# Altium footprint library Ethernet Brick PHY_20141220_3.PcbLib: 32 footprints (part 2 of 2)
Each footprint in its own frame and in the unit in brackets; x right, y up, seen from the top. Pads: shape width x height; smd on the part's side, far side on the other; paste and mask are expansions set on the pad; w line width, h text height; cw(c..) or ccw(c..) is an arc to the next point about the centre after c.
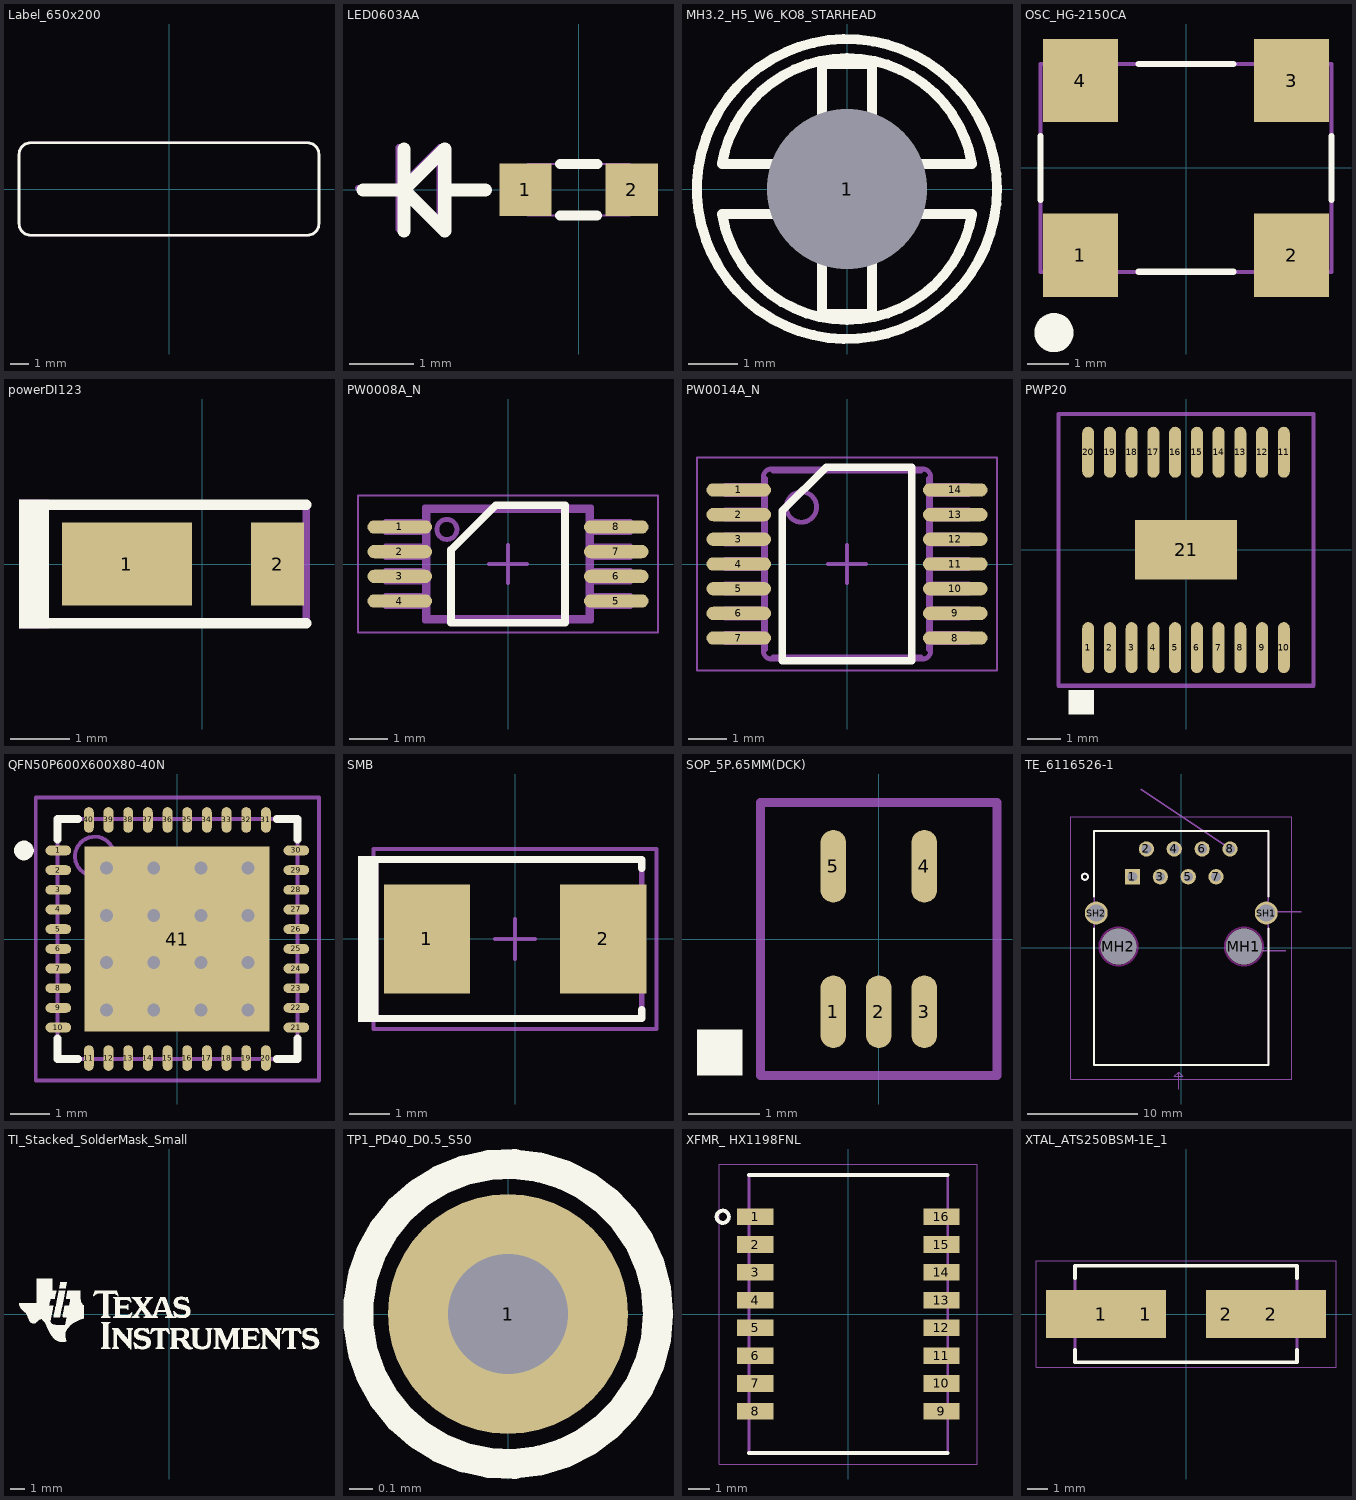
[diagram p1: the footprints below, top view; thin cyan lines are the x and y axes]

## Label_650x200 [mil] "Thermal Transfer Label"
height 1
pads (1):
  round 1 on Mech13: 0(0,0)
Top Overlay:
  lines w6: -325,-75 ccw(c-300,-75) -300,-100 300,-100 ccw(c300,-75) 325,-75 325,75 ccw(c300,75) 300,100 -300,100 ccw(c-300,75) -325,75 -325,-75
Mechanical 5:
  lines w5: -325,-75 ccw(c-300,-75) -300,-100 300,-100 ccw(c300,-75) 325,-75 325,75 ccw(c300,75) 300,100 -300,100 ccw(c-300,75) -325,75 -325,-75
  text ".Designator" at -43,-19.85 h32
3D body: height 1, standoff 0, extent -325.51,-100.51 325.51,100.51

## LED0603AA [mil]
height 35.43
pads (2):
  rect 32x32 smd: 1(-32.48,0) 2(32.48,0)
Top Overlay:
  lines w6: -11.42,-15.75 11.42,-15.75 ; -11.42,15.75 11.42,15.75
  lines w8: -131.79,-0.04 -106.79,-0.04 ; -106.79,-25.04 -106.79,24.96 ; -81.79,-0.04 -56.79,-0.04 ; -106.79,-0.04 -81.79,-25.04 -81.79,24.96 -106.79,-0.04
Mechanical 15:
  lines w1: -31.5,-15.75 -31.5,15.75 31.5,15.75 31.5,-15.75 -31.5,-15.75
  lines w3.94: -134.79,0.96 -109.79,0.96 ; -109.79,-24.04 -109.79,25.96 ; -84.79,0.96 -59.79,0.96 ; -109.79,0.96 -84.79,-24.04 -84.79,25.96 -109.79,0.96

## MH3.2_H5_W6_KO8_STARHEAD [mil]
height 80
pads (1):
  round 20 / inner round 142 / far side round 20 hole 128 unplated mask+68: 1(0,0)
Top Overlay:
  circle w8: c0,0 r120
  lines w8: -100,-20 -20,-20 -20,-100 20,-100 20,-20 100,-20 ; -100.02,-19.91 ccw(c0,-3.35) 99.99,-20.08 ; -100,20 -20,20 -20,100 20,100 20,20 100,20 ; -99.99,20.09 cw(c0,3.36) 100.02,19.92

## OSC_HG-2150CA [mm]
height 1.4
pads (4):
  rect 1.8x2 smd: 1(-2.54,-2.1) 2(2.54,-2.1) 3(2.54,2.1) 4(-2.54,2.1)
Top Overlay:
  circle w0.635: c-3.175,-3.962 r0.152
  lines w0.152: -3.5,-0.762 -3.5,0.762 ; -1.143,-2.5 1.143,-2.5 ; -1.143,2.5 1.143,2.5 ; 3.5,-0.762 3.5,0.762
Mechanical 5:
  circle w0.1: c-2.55,-2.075 r0.2
  lines w0.1: -3.5,-2.5 -3.5,2.5 3.5,2.5 3.5,-2.5 -3.5,-2.5
  text ".Designator" at 0.711,0.225 h0.91
3D body: height 1.2, standoff 1.1, extent -2.685,-2.22 -2.411,-1.946
3D body: height 1.4, standoff 0, extent -3.5,-2.5 3.5,2.5
3D body: height 1.4, standoff 1.1, extent -3.5,-2.5 3.5,2.5

## powerDI123 [mm] "Diodes Inc recommended land pattern, document number DS30628 Rev. 6-2"
height 1
pads (2):
  rect 2.2x1.4 smd: 1(-1.275,0)
  rect 0.9x1.4 smd: 2(1.275,0)
Top Overlay:
  rectangle: -3.099,-1.092 -2.591,1.092
  lines w0.178: -2.946,-1.003 1.759,-1.003 ; -2.946,1.003 1.759,1.003
Mechanical 5:
  rectangle: -3.099,-1.092 -2.591,1.092
  lines w0.127: -2.946,-1.003 1.759,-1.003 1.759,1.003 -2.946,1.003
  text ".Designator" at -1.139,-0.406 h0.91
3D body: height 1, standoff 0, extent -2.375,-0.965 1.525,0.965

## PW0008A_N [mm] "TSOP, 8-Leads, Body 3x4.4mm, Pitch 0.65mm, IPC Medium Density"
height 1.2
pads (8):
  oval 1.7x0.35 smd: 1(-2.85,0.975) 2(-2.85,0.325) 3(-2.85,-0.325) 4(-2.85,-0.975) 5(2.85,-0.975) 6(2.85,-0.325) 7(2.85,0.325) 8(2.85,0.975)
Top Overlay:
  lines w0.2: -1.5,-1.55 1.5,-1.55 1.5,1.55 -0.325,1.55 -1.5,0.375 -1.5,-1.55
Mechanical 5:
  lines w0.127: -2.2,-1.5 -2.11,-1.41 ; -2.2,-1.5 2.2,-1.5 ; -2.2,-1.5 -2.2,-1.125 ; -2.2,-1.125 -2.2,-0.825 ; -2.2,-1.125 -2.4,-1.125 -2.669,-1.125 -2.785,-1.125 -2.856,-1.125 -3.228,-1.125 -3.228,-0.825 -2.856,-0.825 -2.785,-0.825 -2.669,-0.825 -2.4,-0.825 -2.2,-0.825 ; -2.2,-0.825 -2.2,-0.475 ; -2.2,-0.475 -2.4,-0.475 -2.669,-0.475 -2.785,-0.475 -2.856,-0.475 -3.228,-0.475 -3.228,-0.175 -2.856,-0.175 -2.785,-0.175 -2.669,-0.175 -2.4,-0.175 -2.2,-0.175 ; -2.2,-0.475 -2.2,-0.175 ; -2.2,-0.175 -2.2,0.175 ; -2.2,0.175 -2.2,0.475 ; -2.2,0.175 -2.4,0.175 -2.669,0.175 -2.785,0.175 -2.856,0.175 -3.228,0.175 -3.228,0.475 -2.856,0.475 -2.785,0.475 -2.669,0.475 -2.4,0.475 -2.2,0.475 ; -2.2,0.475 -2.2,0.825 ; -2.2,0.825 -2.4,0.825 -2.669,0.825 -2.785,0.825 -2.856,0.825 -3.228,0.825 -3.228,1.125 -2.856,1.125 -2.785,1.125 -2.669,1.125 -2.4,1.125 -2.2,1.125 ; -2.2,0.825 -2.2,1.125 ; -2.2,1.125 -2.2,1.5 ; -2.2,1.5 -2.11,1.41 ; -2.2,1.5 2.2,1.5 ; -2.11,-1.41 -2.11,1.41 ; -2.11,-1.41 2.11,-1.41 ; -2.11,1.41 2.11,1.41 ; 2.11,-1.41 2.11,1.41 ; 2.11,-1.41 2.2,-1.5 ; 2.11,1.41 2.2,1.5 ; 2.2,-1.5 2.2,-1.125 ; 2.2,-1.125 2.2,-0.825 ; 2.2,-1.125 2.4,-1.125 2.669,-1.125 2.785,-1.125 2.856,-1.125 3.228,-1.125 3.228,-0.825 2.856,-0.825 2.785,-0.825 2.669,-0.825 2.4,-0.825 2.2,-0.825 ; 2.2,-0.825 2.2,-0.475 ; 2.2,-0.475 2.2,-0.175 ; 2.2,-0.475 2.4,-0.475 2.669,-0.475 2.785,-0.475 2.856,-0.475 3.228,-0.475 3.228,-0.175 2.856,-0.175 2.785,-0.175 2.669,-0.175 2.4,-0.175 2.2,-0.175 ; 2.2,-0.175 2.2,0.175 ; 2.2,0.175 2.4,0.175 2.669,0.175 2.785,0.175 2.856,0.175 3.228,0.175 3.228,0.475 2.856,0.475 2.785,0.475 2.669,0.475 2.4,0.475 2.2,0.475 ; 2.2,0.175 2.2,0.475 ; 2.2,0.475 2.2,0.825 ; 2.2,0.825 2.4,0.825 2.669,0.825 2.785,0.825 2.856,0.825 3.228,0.825 3.228,1.125 2.856,1.125 2.785,1.125 2.669,1.125 2.4,1.125 2.2,1.125 ; 2.2,0.825 2.2,1.125 ; 2.2,1.125 2.2,1.5 ; -1.61,0.646 cw(c-1.61,0.91) -1.61,1.173 cw(c-1.61,0.91) -1.61,0.646
  text ".Designator" at -0.838,-0.381 h0.91
Mechanical 15:
  lines w0.05: -3.95,-1.8 -3.95,1.8 3.95,1.8 3.95,-1.8 -3.95,-1.8
  lines w0.1: -0.5,0 0.5,0 ; 0,-0.5 0,0.5
3D body: height 1.2, standoff 0, extent -3.228,-1.5 3.228,1.5

## PW0014A_N [mm] "TSOP, 14-Leads, Body 5x4.4mm, Pitch 0.65mm, IPC Medium Density"
height 1.2
pads (14):
  oval 1.7x0.35 smd: 1(-2.85,1.95) 2(-2.85,1.3) 3(-2.85,0.65) 4(-2.85,0) 5(-2.85,-0.65) 6(-2.85,-1.3) 7(-2.85,-1.95) 8(2.85,-1.95) 9(2.85,-1.3) 10(2.85,-0.65) 11(2.85,0) 12(2.85,0.65) 13(2.85,1.3) 14(2.85,1.95)
Top Overlay:
  lines w0.2: -1.7,-2.55 1.7,-2.55 1.7,2.55 -0.55,2.55 -1.7,1.4 -1.7,-2.55
Mechanical 5:
  drawing of 182 lines, arcs and shapes, not listed
  text ".Designator" at 0.432,-0.787 h0.91
Mechanical 15:
  lines w0.05: -3.95,-2.8 -3.95,2.8 3.95,2.8 3.95,-2.8 -3.95,-2.8
  lines w0.1: -0.5,0 0.5,0 ; 0,-0.5 0,0.5
3D body: height 0.98, standoff -0.02, extent -3.21,-2.5 3.21,2.5

## PWP20 [mil]
pads (21):
  oval 14x60 smd: 1(-115.16,-115) 2(-89.57,-115) 3(-63.98,-115) 4(-38.39,-115) 5(-12.8,-115) 6(12.8,-115) 7(38.39,-115) 8(63.98,-115) 9(89.57,-115) 10(115.16,-115) 11(115.16,115) 12(89.57,115) 13(63.98,115) 14(38.39,115) 15(12.8,115) 16(-12.8,115) 17(-38.39,115) 18(-63.98,115) 19(-89.57,115) 20(-115.16,115)
  rect 120x70 smd: 21(0,0)
Top Overlay:
  region: -138,-165.4 -138,-193.15 -108.4,-193.15 -108.4,-165.4
Mechanical 5:
  lines w5: -150,-160 150,-160 150,160 -150,160 -150,-160
  text ".Designator" at 28,14.85 h36
  text "*" at -135,-88.4 h36

## QFN50P600X600X80-40N [mm] "QFN, 40-Leads, Body 6.1x6.1mm (max), Pitch 0.50mm, IPC Medium Density"
height 0.8
pads (41):
  oval 0.65x0.25 smd: 1(-3.025,2.25) 2(-3.025,1.75) 3(-3.025,1.25) 4(-3.025,0.75) 5(-3.025,0.25) 6(-3.025,-0.25) 7(-3.025,-0.75) 8(-3.025,-1.25) 9(-3.025,-1.75) 10(-3.025,-2.25) 21(3.025,-2.25) 22(3.025,-1.75) 23(3.025,-1.25) 24(3.025,-0.75) 25(3.025,-0.25) 26(3.025,0.25) 27(3.025,0.75) 28(3.025,1.25) 29(3.025,1.75) 30(3.025,2.25)
  oval 0.25x0.65 smd: 11(-2.25,-3.025) 12(-1.75,-3.025) 13(-1.25,-3.025) 14(-0.75,-3.025) 15(-0.25,-3.025) 16(0.25,-3.025) 17(0.75,-3.025) 18(1.25,-3.025) 19(1.75,-3.025) 20(2.25,-3.025) 31(2.25,3.025) 32(1.75,3.025) 33(1.25,3.025) 34(0.75,3.025) 35(0.25,3.025) 36(-0.25,3.025) 37(-0.75,3.025) 38(-1.25,3.025) 39(-1.75,3.025) 40(-2.25,3.025)
  rect 4.7x4.7 smd: 41(-0.006,0)
via -1.8,1.8 diameter 0.66 hole 0.33
via -0.6,1.8 diameter 0.66 hole 0.33
via 0.6,1.8 diameter 0.66 hole 0.33
via 1.8,1.8 diameter 0.66 hole 0.33
via -1.8,0.6 diameter 0.66 hole 0.33
via -0.6,0.6 diameter 0.66 hole 0.33
via 0.6,0.6 diameter 0.66 hole 0.33
via 1.8,0.6 diameter 0.66 hole 0.33
via -1.8,-0.6 diameter 0.66 hole 0.33
via -0.6,-0.6 diameter 0.66 hole 0.33
via 0.6,-0.6 diameter 0.66 hole 0.33
via 1.8,-0.6 diameter 0.66 hole 0.33
via -1.8,-1.8 diameter 0.66 hole 0.33
via -0.6,-1.8 diameter 0.66 hole 0.33
via 0.6,-1.8 diameter 0.66 hole 0.33
via 1.8,-1.8 diameter 0.66 hole 0.33
Top Overlay:
  circle w0.25: c-3.9,2.25 r0.125
  lines w0.2: -3.05,-2.525 -3.05,-3.05 -2.525,-3.05 ; -3.05,2.525 -3.05,3.05 -2.525,3.05 ; 2.525,-3.05 3.05,-3.05 3.05,-2.525 ; 2.525,3.05 3.05,3.05 3.05,2.525
Mechanical 13:
  circle w0.1: c-2.1,2.1 r0.5
  lines w0.1: -3.05,-3.05 -3.05,3.05 3.05,3.05 3.05,-3.05 -3.05,-3.05
Mechanical 15:
  lines w0.1: -0.5,0 0.5,0 ; 0,-0.5 0,0.5 ; -3.6,-3.6 -3.6,3.6 3.6,3.6 3.6,-3.6 -3.6,-3.6
3D body: height 0.8, standoff 0.1, extent -3.05,-3.05 3.05,3.05

## SMB [mm] "Molded Diode, 2-Leads, Body 5.4x3.6mm, IPC Medium Density, based on OnSemi component dimensions"
height 2.45
pads (2):
  rect 2.159x2.743 smd: 1(-2.21,0) 2(2.21,0)
Top Overlay:
  rectangle: -3.937,-2.083 -3.429,2.083
  lines w0.178: -3.607,-1.994 3.175,-1.994 3.175,-1.765 ; -3.607,1.994 3.175,1.994 3.175,1.765
Mechanical 5:
  rectangle: -3.937,-2.083 -3.429,2.083
  lines w0.127: -3.607,-1.994 3.175,-1.994 3.175,-1.765 3.175,1.765 3.175,1.994 -3.607,1.994
  text ".Designator" at -0.813,-0.508 h0.91
Mechanical 15:
  lines w0.1: -0.5,0 0.5,0 ; 0,-0.5 0,0.5 ; -3.55,-2.25 -3.55,2.25 3.55,2.25 3.55,-2.25 -3.55,-2.25
3D body: height 2.32, standoff 0.02, extent -2.7,-1.8 2.7,1.8

## SOP_5P.65MM(DCK) [mil]
pads (5):
  oval 14x40 smd mask+2: 1(-25,-40) 2(0,-40) 3(25,-40) 4(25,40) 5(-25,40)
Top Overlay:
  region: -100,-75 -75,-75 -75,-50 -100,-50
Mechanical 5:
  lines w5: -65,-75 -65,75 65,75 65,-75 -65,-75
  text ".Designator" at 20,17 h36
  text "*" at -55,-75 h36

## TE_6116526-1 [mm] "CONNECTOR, MODULAR JACK SHIELDED R/A, THRU-8 PIN"
height 13.63
pads (12):
  rect 1.39x1.39 hole 0.89: 1(-4.445,6.48)
  round 1.39 hole 0.89: 2(-3.175,9.02) 3(-1.905,6.48) 4(-0.635,9.02) 5(0.635,6.48) 6(1.905,9.02) 7(3.175,6.48) 8(4.445,9.02)
  round 3.25 hole 3.25 unplated mask+0.305: MH1(5.715,0.13) MH2(-5.715,0.13)
  round 2.08 hole 1.58: SH1(7.745,3.18) SH2(-7.745,3.18)
Top Overlay:
  circle w0.178: c-8.774,6.485 r0.279
  lines w0.178: -7.93,1.781 -7.93,-10.67 7.93,-10.67 7.93,1.781 ; -7.93,4.702 -7.93,10.671 7.93,10.67 7.93,4.702
Bottom Overlay:
  lines w0.178: -7.93,-9.274 -7.93,-10.67 -6.534,-10.67 ; -7.93,-8.004 -7.93,-6.607 ; -7.93,-5.972 -7.93,-4.702 ; -7.93,-1.032 -7.93,0.238 ; -7.93,1.127 -7.93,1.781 ; -7.93,4.702 -7.93,5.972 ; -7.93,6.607 -7.93,8.004 ; -7.93,9.274 -7.93,10.67 -6.534,10.67 ; -7.929,-3.629 -7.929,-2.359 ; -5.264,-10.67 -3.867,-10.67 ; -5.264,10.67 -3.867,10.67 ; -3.232,-10.67 -1.962,-10.67 ; -3.232,10.67 -1.962,10.67 ; -0.762,-10.669 0.508,-10.669 ; -0.762,10.671 0.508,10.671 ; 1.962,-10.67 3.232,-10.67 ; 1.962,10.67 3.232,10.67 ; 3.867,-10.67 5.264,-10.67 ; 3.867,10.67 5.264,10.67 ; 6.534,-10.67 7.93,-10.67 7.93,-9.274 ; 6.534,10.67 7.93,10.67 7.93,9.274 ; 7.93,-8.004 7.93,-6.607 ; 7.93,-5.972 7.93,-4.702 ; 7.93,-1.156 7.93,0.114 ; 7.93,1.127 7.93,1.781 ; 7.93,4.702 7.93,5.972 ; 7.93,6.607 7.93,8.004 ; 7.931,-3.502 7.931,-2.232
Keep-Out Layer:
  circle w0.178: c-5.715,0.13 r1.727
  circle w0.178: c5.715,0.13 r1.727
Mechanical 5:
  circle w0.127: c-8.774,6.485 r0.279
  lines w0.127: -7.93,-10.67 7.93,-10.67 7.93,10.67 -7.93,10.67 -7.93,-10.67
  text ".Designator" at -0.787,2.365 h0.91
Mechanical 15:
  lines w0.05: -10.055,-11.94 -10.055,11.94 10.055,11.94 10.055,-11.94 -10.055,-11.94
Mechanical 16:
  lines w0.05: -0.245,-12.848 -0.245,-11.324 ; -0.245,-11.324 0.136,-11.705 -0.626,-11.705 -0.245,-11.324
  lines w0.127: -3.683,14.478 4.445,9.02 ; 6.985,-0.254 9.525,-0.254 ; 8.382,3.302 10.922,3.302
Mechanical 17:
  text "MATING CONNECTOR SIDE" at -9.516,-15.134 h1
  text "2X DRILL TOLERANCE FOR 3.25 MM DRILL TO BE +0.08/-0.05 MM" at 9.771,-0.87 h1.52
  text "8X DRILL TOLERANCE FOR 0.89 MM DRILL TO BE +/-0.08 MM" at -39.632,14.497 h1.52
  text "PCB EDGE THIS SIDE" at -8.5,-13.483 h1
  text "LEAD LENGTH: 3.56 MM" at -9.53,-5.023 h1
  text "2X DRILL TOLERANCE FOR 1.58 MM DRILL TO BE +/-0.08 MM" at 11.168,2.686 h1.52
3D body: height 6.75, standoff -10.82, extent -7.937,-10.67 7.938,10.666

## TI_Stacked_SolderMask_Small [mm]
Top Overlay:
  drawing of 18 lines, arcs and shapes, not listed

## TP1_PD40_D0.5_S50 [mil]
height 1.4
pads (1):
  round 40 hole 20: 1(0,0)
Top Overlay:
  circle w5: c0,0 r25

## XFMR_ HX1198FNL [mm] "TRANSFORMER, MODULE XFMR, 16-SOIC"
height 5.99
pads (16):
  rect 1.65x0.76 smd: 1(-4.255,4.445) 2(-4.255,3.175) 3(-4.255,1.905) 4(-4.255,0.635) 5(-4.255,-0.635) 6(-4.255,-1.905) 7(-4.255,-3.175) 8(-4.255,-4.445) 9(4.255,-4.445) 10(4.255,-3.175) 11(4.255,-1.905) 12(4.255,-0.635) 13(4.255,0.635) 14(4.255,1.905) 15(4.255,3.175) 16(4.255,4.445)
Top Overlay:
  circle w0.178: c-5.74,4.445 r0.279
  lines w0.178: -4.547,-6.35 4.547,-6.35 ; -4.547,6.35 4.547,6.35
Mechanical 5:
  circle w0.127: c-5.74,4.445 r0.279
  lines w0.127: -4.547,-6.35 -4.547,6.35 4.547,6.35 4.547,-6.35 -4.547,-6.35
  text ".Designator" at 0.533,-0.914 h0.91
Mechanical 15:
  lines w0.05: -5.9,-6.858 5.9,-6.858 5.9,6.858 -5.9,6.858 -5.9,-6.858
3D body: height 5.99, standoff 0, extent -4.547,-6.35 4.547,6.35

## XTAL_ATS250BSM-1E_1 [mm] "CRYSTAL, SMD-2P"
height 4.3
pads (4):
  rect 5.5x2.4 smd: 1(-4.25,0) 2(4.25,0)
  rect 2x2.4 smd: 1(-2,0) 2(2,0)
Top Overlay:
  lines w0.178: -5.55,-1.778 -5.55,-2.415 5.55,-2.415 5.55,-1.778 ; -5.55,1.778 -5.55,2.415 5.55,2.415 5.55,1.778
Mechanical 5:
  lines w0.127: -5.55,-2.415 -5.55,2.415 5.55,2.415 5.55,-2.415 -5.55,-2.415
  text ".Designator" at 0.394,-0.711 h0.91
Mechanical 15:
  lines w0.05: -7.5,-2.665 7.5,-2.665 7.5,2.665 -7.5,2.665 -7.5,-2.665
3D body: height 4.3, standoff 0, extent -5.55,-2.415 5.55,2.415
